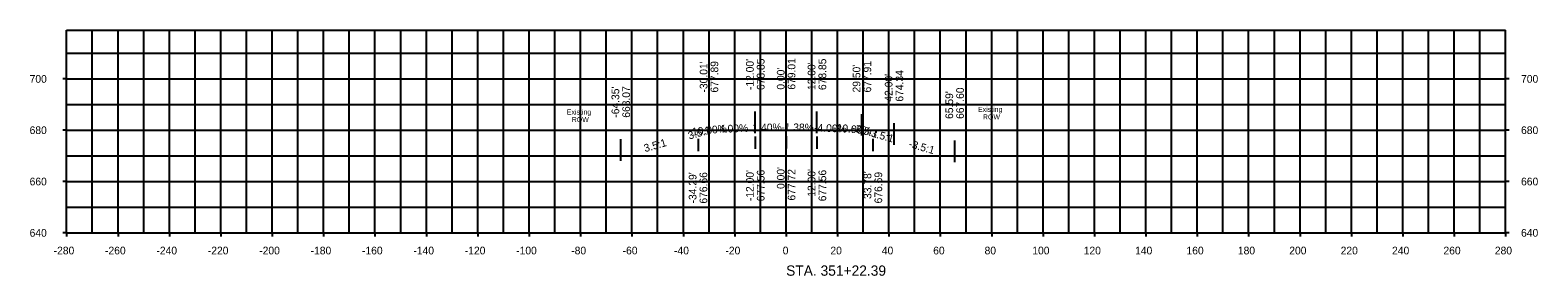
# Model space of a CAD drawing. Extents: x -294 to 293, y 623 to 719.
import ezdxf

# ---------------------------------------------------------------- set-up
doc = ezdxf.new("R2010")
doc.units = 0
for name, color, linetype in [('Default', 7, 'Continuous'), ('PS_BOLT', 7, 'Continuous'), ('PS_DIM', 7, 'Continuous'), ('PS_PLATE', 7, 'Continuous'), ('PS_TEXT', 7, 'Continuous'), ('PS_WORKFRAME', 7, 'Continuous')]:
    doc.layers.add(name, color=color, linetype=linetype)

msp = doc.modelspace()

# ---------------------------------------------------------------- linework, layer by layer
at = {"layer": 'PS_BOLT'}
for p, q in [((-260, 640), (-260, 719.02)), ((-240, 640), (-240, 719.02)), ((-220, 640), (-220, 719.02)), ((-200, 640), (-200, 719.02)), ((-180, 640), (-180, 719.02)), ((-160, 640), (-160, 719.02)), ((-140, 640), (-140, 719.02)), ((-120, 640), (-120, 719.02)), ((-100, 640), (-100, 719.02)), ((-80, 640), (-80, 719.02)), ((-60, 640), (-60, 719.02)), ((-40, 640), (-40, 719.02)), ((-20, 640), (-20, 719.02)), ((0, 640), (0, 719.02)), ((20, 640), (20, 719.02)), ((40, 640), (40, 719.02)), ((60, 640), (60, 719.02)), ((80, 640), (80, 719.02)), ((100, 640), (100, 719.02)), ((120, 640), (120, 719.02)), ((140, 640), (140, 719.02)), ((160, 640), (160, 719.02)), ((180, 640), (180, 719.02)), ((200, 640), (200, 719.02)), ((220, 640), (220, 719.02)), ((240, 640), (240, 719.02)), ((260, 640), (260, 719.02)), ((-280, 700), (-281.44, 700)), ((-280, 700), (280, 700)), ((281.44, 700), (280, 700)), ((-280, 680), (-281.44, 680)), ((-280, 680), (280, 680)), ((281.44, 680), (280, 680)), ((-280, 660), (-281.44, 660)), ((-280, 660), (280, 660)), ((281.44, 660), (280, 660)), ((-280, 640), (-281.44, 640)), ((-280, 640), (-280, 638.56)), ((-260, 640), (-260, 638.56)), ((-240, 640), (-240, 638.56)), ((-220, 640), (-220, 638.56)), ((-200, 640), (-200, 638.56)), ((-180, 640), (-180, 638.56)), ((-160, 640), (-160, 638.56)), ((-140, 640), (-140, 638.56)), ((-120, 640), (-120, 638.56)), ((-100, 640), (-100, 638.56)), ((-80, 640), (-80, 638.56)), ((-60, 640), (-60, 638.56)), ((-40, 640), (-40, 638.56)), ((-20, 640), (-20, 638.56)), ((0, 640), (0, 638.56)), ((20, 640), (20, 638.56)), ((40, 640), (40, 638.56)), ((60, 640), (60, 638.56)), ((80, 640), (80, 638.56)), ((100, 640), (100, 638.56)), ((120, 640), (120, 638.56)), ((140, 640), (140, 638.56)), ((160, 640), (160, 638.56)), ((180, 640), (180, 638.56)), ((200, 640), (200, 638.56)), ((220, 640), (220, 638.56)), ((240, 640), (240, 638.56)), ((260, 640), (260, 638.56)), ((280, 640), (280, 638.56)), ((281.44, 640), (280, 640))]:
    msp.add_line(p, q, dxfattribs=at)
at = {"layer": 'PS_DIM'}
for p, q in [((-270, 640), (-270, 719.02)), ((-250, 640), (-250, 719.02)), ((-230, 640), (-230, 719.02)), ((-210, 640), (-210, 719.02)), ((-190, 640), (-190, 719.02)), ((-170, 640), (-170, 719.02)), ((-150, 640), (-150, 719.02)), ((-130, 640), (-130, 719.02)), ((-110, 640), (-110, 719.02)), ((-90, 640), (-90, 719.02)), ((-70, 640), (-70, 719.02)), ((-50, 640), (-50, 719.02)), ((-30, 640), (-30, 719.02)), ((-10, 640), (-10, 719.02)), ((10, 640), (10, 719.02)), ((30, 640), (30, 719.02)), ((50, 640), (50, 719.02)), ((70, 640), (70, 719.02)), ((90, 640), (90, 719.02)), ((110, 640), (110, 719.02)), ((130, 640), (130, 719.02)), ((150, 640), (150, 719.02)), ((170, 640), (170, 719.02)), ((190, 640), (190, 719.02)), ((210, 640), (210, 719.02)), ((230, 640), (230, 719.02)), ((250, 640), (250, 719.02)), ((270, 640), (270, 719.02)), ((-280, 710), (280, 710)), ((-280, 690), (280, 690)), ((-280, 670), (280, 670)), ((-280, 650), (280, 650))]:
    msp.add_line(p, q, dxfattribs=at)
at = {"layer": 'PS_PLATE'}
for p, q in [((-280, 719.02), (280, 719.02)), ((-280, 640), (-280, 719.02)), ((280, 640), (280, 719.02)), ((-280, 640), (280, 640))]:
    msp.add_line(p, q, dxfattribs=at)
at = {"layer": 'PS_TEXT'}
for p, q in [((-80.14, 682.73), (-80.14, 658.13)), ((79.89, 683.76), (79.89, 659.16))]:
    msp.add_line(p, q, dxfattribs=at)
at = {"layer": 'PS_WORKFRAME'}
for p, q in [((-12, 678.85), (-12, 687.25)), ((0, 679.01), (0, 687.41)), ((12, 678.85), (12, 687.25)), ((-30.01, 677.89), (-30.01, 686.29)), ((29.5, 677.91), (29.5, 686.31)), ((42, 674.34), (42, 682.74)), ((-64.35, 668.07), (-64.35, 676.47)), ((-64.35, 668.07), (-64.35, 676.47)), ((-34.29, 676.66), (-34.29, 671.86)), ((-12, 677.56), (-12, 672.76)), ((0, 677.72), (0, 672.92)), ((12, 677.56), (12, 672.76)), ((33.78, 676.69), (33.78, 671.89)), ((65.59, 667.6), (65.59, 676))]:
    msp.add_line(p, q, dxfattribs=at)

# ---------------------------------------------------------------- texts
at = {"layer": 'Default'}
for s, height, p in [('700', 3, (-294.4, 698.5)), ('700', 3, (286, 698.5)), ('680', 3, (-294.4, 678.5)), ('680', 3, (286, 678.5)), ('660', 3, (-294.4, 658.5)), ('660', 3, (286, 658.5)), ('640', 3, (-294.4, 638.5)), ('640', 3, (286, 638.5)), ('-280', 3, (-285.05, 631.6)), ('-260', 3, (-265.05, 631.6)), ('-240', 3, (-245.05, 631.6)), ('-220', 3, (-225.05, 631.6)), ('-200', 3, (-205.05, 631.6)), ('-180', 3, (-185.05, 631.6)), ('-160', 3, (-165.05, 631.6)), ('-140', 3, (-145.05, 631.6)), ('-120', 3, (-125.05, 631.6)), ('-100', 3, (-105.05, 631.6)), ('-80', 3, (-83.62, 631.6)), ('-60', 3, (-63.62, 631.6)), ('-40', 3, (-43.62, 631.6)), ('-20', 3, (-23.62, 631.6)), ('0', 3, (-1.33, 631.6)), ('20', 3, (17.23, 631.6)), ('40', 3, (37.23, 631.6)), ('60', 3, (57.23, 631.6)), ('80', 3, (77.23, 631.6)), ('100', 3, (95.8, 631.6)), ('120', 3, (115.8, 631.6)), ('140', 3, (135.8, 631.6)), ('160', 3, (155.8, 631.6)), ('180', 3, (175.8, 631.6)), ('200', 3, (195.8, 631.6)), ('220', 3, (215.8, 631.6)), ('240', 3, (235.8, 631.6)), ('260', 3, (255.8, 631.6)), ('280', 3, (275.8, 631.6)), ('STA. 351+22.39', 4.008, (0, 623.28))]:
    msp.add_text(s, height=height, dxfattribs=at).set_placement(p)
at = {"layer": 'PS_TEXT'}
for s, p in [('Existing', (-85.36, 686.12)), ('Existing', (74.66, 687.14)), ('ROW', (-83.43, 683.16)), ('ROW', (76.6, 684.19))]:
    msp.add_text(s, height=1.969, dxfattribs=at).set_placement(p)
at = {"layer": 'PS_WORKFRAME'}
for s, rotation, p in [("-30.01'", 90, (-30.61, 694.69)), ('677.89', 90, (-26.41, 694.69)), ("-12.00'", 90, (-12.6, 695.65)), ('678.85', 90, (-8.4, 695.65)), ("0.00'", 90, (-0.6, 695.81)), ('679.01', 90, (3.6, 695.81)), ("12.00'", 90, (11.4, 695.65)), ('678.85', 90, (15.6, 695.65)), ("29.50'", 90, (28.9, 694.71)), ('677.91', 90, (33.1, 694.71)), ("42.00'", 90, (41.4, 691.14)), ('674.34', 90, (45.6, 691.14)), ("-64.35'", 90, (-64.95, 684.87)), ("-64.35'", 90, (-64.95, 684.87)), ('668.07', 90, (-60.75, 684.87)), ('668.07', 90, (-60.75, 684.87)), ("65.59'", 90, (64.99, 684.4)), ('667.60', 90, (69.19, 684.4)), ('3.5:1', 15.9454, (-37.7, 676.35)), ('10.00%', 5.71059, (-36.48, 677.9)), ('4.00%', 2.29061, (-26.07, 678.94)), ('1.40%', 0.80028, (-13.08, 679.49)), ('-1.38%', 359.20835, (-1.93, 679.7)), ('-4.00%', 357.70939, (10.83, 679.55)), ('-10.00%', 354.28941, (18.19, 679.7)), ('-3.5:1', 344.0546, (25.3, 679.77)), ('3.5:1', 15.9454, (-54.87, 671.44)), ('-3.5:1', 344.0546, (31.55, 677.98)), ('-3.5:1', 344.0546, (47.45, 673.44)), ("-34.29'", 90, (-34.89, 651.47)), ('676.66', 90, (-30.69, 651.4)), ("-12.00'", 90, (-12.6, 652.36)), ('677.56', 90, (-8.4, 652.29)), ("0.00'", 90, (-0.6, 657.1)), ('677.72', 90, (3.6, 652.6)), ("12.00'", 90, (11.4, 654.07)), ('677.56', 90, (15.6, 652.3)), ("33.78'", 90, (33.18, 653.2)), ('676.69', 90, (37.38, 651.47))]:
    msp.add_text(s, height=3, rotation=rotation, dxfattribs=at).set_placement(p)

doc.saveas('drawing.dxf')
